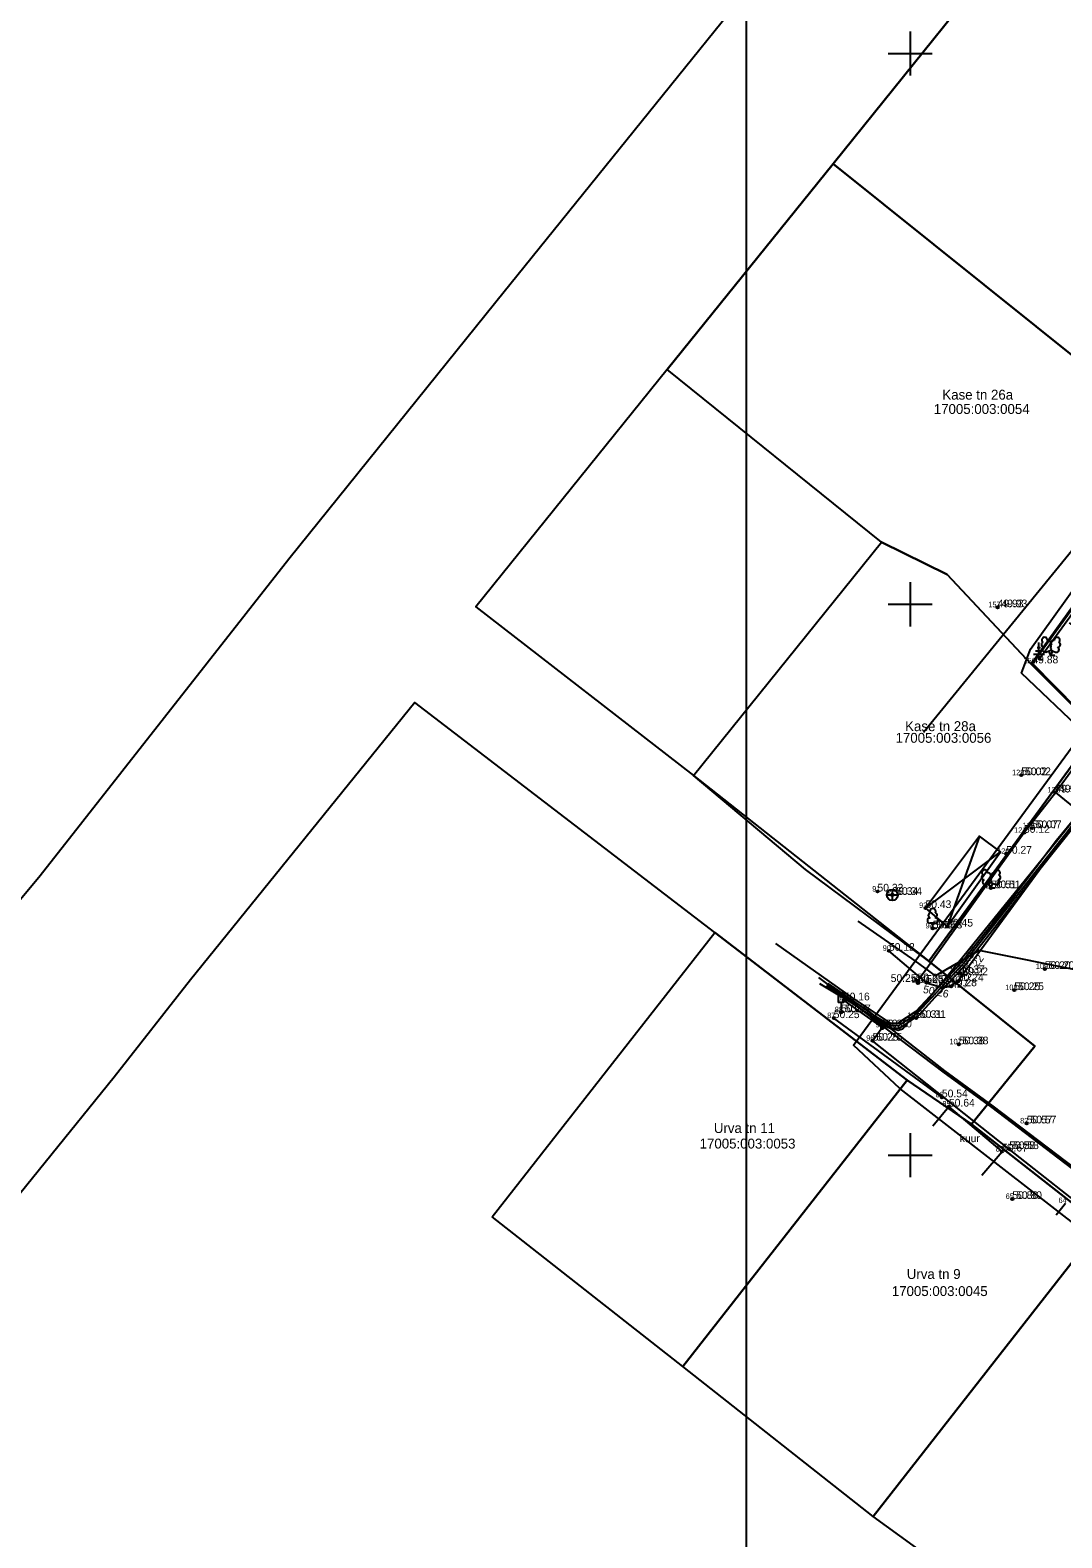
# Model space of a CAD drawing. Extents: x 640876 to 641418, y 6455595 to 6456085.
# Drawn here: x 640970.1 to 641063.8, y 6455815.3 to 6455952.1 of the extents above; entities that cross this region are included whole.
import ezdxf

# ---------------------------------------------------------------- set-up
doc = ezdxf.new("R2010")
doc.units = 0
for name, color, linetype in [('AED', 7, 'Continuous'), ('HALJASTUS', 7, 'Continuous'), ('HOONE', 7, 'Continuous'), ('KKAEV', 7, 'Continuous'), ('KORGUS', 7, 'Continuous'), ('KPKAABEL', 7, 'Continuous'), ('KTRASS', 7, 'Continuous'), ('LIIKLUS', 7, 'Continuous'), ('MOOTKORG', 7, 'Continuous'), ('MOOTMPUNKT', 7, 'Continuous'), ('MOOTNR', 7, 'Continuous'), ('MOOTPIIR', 7, 'Continuous'), ('MPKAABEL', 7, 'Continuous'), ('PIIR', 7, 'Continuous'), ('PUU', 7, 'Continuous'), ('RAJATIS', 7, 'Continuous'), ('SITRASS', 7, 'Continuous'), ('TEE', 7, 'Continuous'), ('VORK', 7, 'Continuous'), ('VORMISTUS', 7, 'Continuous')]:
    doc.layers.add(name, color=color, linetype=linetype)

msp = doc.modelspace()

# ---------------------------------------------------------------- linework, layer by layer
at = {"layer": 'AED'}
for p, q in [((641050.54, 6455865.9), (641050.54, 6455865.65)), ((641050.54, 6455865.9), (641050.79, 6455865.9)), ((641050.54, 6455865.65), (641050.79, 6455865.65)), ((641050.79, 6455865.9), (641050.79, 6455865.65)), ((641047.33, 6455861.72), (641047.33, 6455861.47)), ((641047.33, 6455861.72), (641047.58, 6455861.72)), ((641047.33, 6455861.47), (641047.58, 6455861.47)), ((641047.58, 6455861.72), (641047.58, 6455861.47))]:
    msp.add_line(p, q, dxfattribs=at)
for points in [[(641063.18, 6455882.92), (641067.22, 6455888.43), (641061.1, 6455894.64), (641102.57, 6455951.87), (641103.76, 6455952.95), (641094.12, 6455962.86), (641083.8, 6455973.39)], [(641050.66, 6455865.78), (641060.33, 6455879.26), (641063.18, 6455882.92), (641066.94, 6455879.86)], [(641058.99, 6455850.55), (641046.59, 6455860.39), (641047.46, 6455861.6)], [(641098.57, 6455819.56), (641094.24, 6455822.82), (641082.1, 6455832.09), (641075.84, 6455837.02), (641067.38, 6455843.96), (641058.99, 6455850.55)]]:
    msp.add_lwpolyline(points, dxfattribs=at)
at = {"layer": 'HALJASTUS'}
msp.add_lwpolyline([(641052.88, 6455855.25), (641043.06, 6455862.44)], dxfattribs=at)
at = {"layer": 'HOONE'}
for points in [[(641053.36, 6455870.75), (641058.2, 6455877.53), (641056.28, 6455878.95), (641051.39, 6455872.43), (641058.2, 6455877.53)], [(641056.28, 6455878.95), (641053.36, 6455870.75)], [(641051.39, 6455872.43), (641053.36, 6455870.75)]]:
    msp.add_lwpolyline(points, dxfattribs=at)
at = {"layer": 'KKAEV'}
for p, q in [((641048.38, 6455873.12), (641048.38, 6455874.12)), ((641047.88, 6455873.62), (641048.88, 6455873.62))]:
    msp.add_line(p, q, dxfattribs=at)
msp.add_circle((641048.38, 6455873.62), 0.5, dxfattribs=at)
at = {"layer": 'KORGUS'}
for centre in [(641057.94, 6455899.73), (641060.08, 6455884.49), (641063.18, 6455882.92), (641061.06, 6455879.68), (641048.38, 6455873.62), (641057.32, 6455874.23), (641052.04, 6455870.58), (641062.22, 6455866.9), (641050.66, 6455865.78), (641051.48, 6455865.64), (641054.42, 6455866.52), (641054.72, 6455866.33), (641059.45, 6455864.98), (641043.72, 6455862.97), (641047.46, 6455861.6), (641050.54, 6455862.45), (641046.59, 6455860.39), (641054.41, 6455860.06), (641060.58, 6455852.88), (641058.99, 6455850.55), (641059.27, 6455846.02)]:
    msp.add_circle(centre, 0.1, dxfattribs=at)
at = {"layer": 'KPKAABEL'}
msp.add_lwpolyline([(641067.36, 6455890.93), (641068.5, 6455889.92), (641069.73, 6455887.97), (641069.93, 6455887.18), (641069.78, 6455886.51), (641069.78, 6455886.51), (641066.43, 6455882.38), (641063.29, 6455878.55), (641061.39, 6455876.05), (641058.5, 6455872.31), (641054.68, 6455867.52), (641050.5, 6455863.04), (641048.84, 6455861.94), (641048.28, 6455861.96), (641044.86, 6455864.23), (641037.79, 6455869.22)], dxfattribs=at)
at = {"layer": 'KTRASS'}
msp.add_lwpolyline([(641090.81, 6455936.84), (641051.22, 6455888.36)], dxfattribs=at)
at = {"layer": 'LIIKLUS'}
for p, q in [((641043.47, 6455864.72), (641043.47, 6455863.87)), ((641043.97, 6455864.72), (641043.47, 6455864.72)), ((641043.97, 6455864.72), (641043.97, 6455863.87)), ((641043.97, 6455863.87), (641043.47, 6455863.87)), ((641043.72, 6455863.87), (641043.72, 6455862.97)), ((641043.97, 6455862.97), (641043.72, 6455862.97))]:
    msp.add_line(p, q, dxfattribs=at)
at = {"layer": 'MOOTMPUNKT'}
for centre in [(641057.94, 6455899.73), (641061.1, 6455894.64), (641060.08, 6455884.49), (641063.18, 6455882.92), (641060.33, 6455879.26), (641061.06, 6455879.68), (641058.71, 6455877.36), (641047.03, 6455873.93), (641048.38, 6455873.62), (641057.32, 6455874.23), (641051.39, 6455872.43), (641052.04, 6455870.58), (641053.36, 6455870.75), (641048.07, 6455868.55), (641062.22, 6455866.9), (641050.66, 6455865.78), (641050.7, 6455865.63), (641051.48, 6455865.64), (641054.33, 6455865.78), (641054.42, 6455866.52), (641054.72, 6455866.33), (641043.98, 6455864.05), (641052.94, 6455865.21), (641053.71, 6455865.33), (641059.45, 6455864.98), (641043.72, 6455862.97), (641043.06, 6455862.44), (641047.46, 6455861.6), (641050.54, 6455862.45), (641046.59, 6455860.39), (641054.41, 6455860.06), (641052.88, 6455855.25), (641053.52, 6455854.41), (641060.58, 6455852.88), (641058.99, 6455850.55), (641058.34, 6455850.33), (641059.27, 6455846.02)]:
    msp.add_circle(centre, 0.1, dxfattribs=at)
at = {"layer": 'MOOTPIIR'}
msp.add_lwpolyline([(641136.35, 6455788.31), (641049.07, 6455856.04), (641044.86, 6455859.98), (641065.69, 6455888.44), (641060.1, 6455893.75), (641060.92, 6455895.94), (641100.06, 6455950.48)], dxfattribs=at)
at = {"layer": 'MPKAABEL'}
for points in [[(641067.96, 6455891.74), (641070.7, 6455889.61), (641070.81, 6455888.61), (641070.19, 6455887.41), (641069.57, 6455886.21), (641066.43, 6455882.38), (641061.37, 6455876.11), (641052.96, 6455865.72), (641049.31, 6455861.43), (641048.91, 6455861.3), (641048, 6455861.6), (641046.5, 6455862.62), (641045, 6455863.65), (641041.69, 6455866.14)], [(641068.21, 6455892.08), (641071.09, 6455889.83), (641071.22, 6455888.51), (641069.95, 6455886.1), (641066.87, 6455882.33), (641061.65, 6455875.78), (641057.25, 6455870.13), (641054.99, 6455867.25), (641052.24, 6455864.31), (641050.77, 6455862.72), (641048.96, 6455861.51), (641048.15, 6455861.54), (641047.48, 6455861.95), (641046.81, 6455862.35), (641044.62, 6455863.88), (641042.42, 6455865.4)], [(641068.08, 6455891.91), (641070.89, 6455889.71), (641071.02, 6455888.57), (641069.74, 6455886.1), (641066.6, 6455882.27), (641061.55, 6455875.93), (641057.24, 6455870.41), (641054.83, 6455867.39), (641050.62, 6455862.89), (641048.9, 6455861.73), (641048.21, 6455861.76), (641046.94, 6455862.54), (641044.75, 6455864.06), (641042.56, 6455865.59)], [(641086.41, 6455829.53), (641086.97, 6455831.37), (641086.62, 6455832.08), (641057.43, 6455854.32), (641053.1, 6455857.47), (641049.11, 6455860.51), (641045.12, 6455863.55), (641041.8, 6455865.56)], [(641086.41, 6455829.53), (641087.32, 6455831.35), (641087.2, 6455831.92), (641057.52, 6455854.46), (641053.15, 6455857.64), (641049.7, 6455860.36), (641046.25, 6455863.08), (641042.44, 6455865.41)]]:
    msp.add_lwpolyline(points, dxfattribs=at)
at = {"layer": 'PIIR'}
for points in [[(640876.41, 6455757.97), (640962.33, 6455865.02), (640971.01, 6455875.38), (640993.57, 6455904.12), (641012.36, 6455927.46), (641024.93, 6455943.02), (641037.5, 6455958.58), (641063.25, 6455990.48), (641061.51, 6455993.34), (641084.84, 6455991.92)], [(641074.95, 6455979.64), (641043, 6455940), (641027.94, 6455921.32), (641010.57, 6455899.76), (641030.33, 6455884.46), (641051.68, 6455867.61), (641061.31, 6455859.9), (641055.55, 6455852.8), (641049.71, 6455856.81), (641032.25, 6455870.2), (641005.01, 6455891.09), (640984.64, 6455865.92), (640977.72, 6455857.07), (640952.64, 6455826.1), (640933.13, 6455802.02)]]:
    msp.add_lwpolyline(points, dxfattribs=at)
for points in [[(641074.95, 6455979.64), (641102.26, 6455951.82), (641075.14, 6455914.24), (641043, 6455940)], [(641098.62, 6455818.85), (641093.41, 6455823.22), (641084.65, 6455830.08), (641067.32, 6455843.61), (641055.55, 6455852.8), (641061.31, 6455859.9), (641051.68, 6455867.61), (641067, 6455888.54), (641060.97, 6455894.57), (641075.14, 6455914.24), (641087.11, 6455930.82), (641102.26, 6455951.82), (641160.91, 6455891.99), (641157.02, 6455885.66), (641139.49, 6455869), (641124.05, 6455849.81)], [(641043, 6455940), (641075.14, 6455914.24), (641060.97, 6455894.57), (641053.35, 6455902.7), (641047.4, 6455905.63), (641027.94, 6455921.32)], [(641040.49, 6455875.93), (641030.33, 6455884.46), (641047.4, 6455905.63), (641053.35, 6455902.7), (641060.97, 6455894.57), (641067, 6455888.54), (641051.68, 6455867.61)], [(641012.04, 6455844.39), (641032.25, 6455870.2), (641049.71, 6455856.81), (641029.34, 6455830.8)], [(641029.34, 6455830.8), (641049.71, 6455856.81), (641055.55, 6455852.8), (641067.32, 6455843.61), (641046.64, 6455817.21)], [(641067.32, 6455843.61), (641084.65, 6455830.08), (641064.46, 6455804.29), (641046.64, 6455817.21)]]:
    msp.add_lwpolyline(points, close=True, dxfattribs=at)
at = {"layer": 'PUU'}
for p, q in [((641061.99, 6455895.75), (641061.39, 6455895.75)), ((641061.84, 6455896.05), (641061.54, 6455896.05)), ((641061.69, 6455894.95), (641061.69, 6455896.53)), ((641062.32, 6455895.67), (641062.77, 6455895.85)), ((641062.76, 6455895.34), (641062.58, 6455895.78)), ((641062.76, 6455895.34), (641062.94, 6455895.78)), ((641062.77, 6455895.85), (641063.2, 6455895.67)), ((641062.19, 6455895.45), (641061.19, 6455895.45)), ((641062.05, 6455894.95), (641061.69, 6455894.95)), ((641063.14, 6455895.34), (641062.76, 6455895.34)), ((641056.88, 6455874.56), (641057.33, 6455874.74)), ((641057.32, 6455874.23), (641057.15, 6455874.67)), ((641057.32, 6455874.23), (641057.5, 6455874.67)), ((641057.7, 6455874.23), (641057.32, 6455874.23)), ((641057.33, 6455874.74), (641057.77, 6455874.56)), ((641052.28, 6455871.06), (641051.8, 6455871.06)), ((641052.04, 6455870.58), (641052.04, 6455871.06)), ((641052.42, 6455870.58), (641052.04, 6455870.58))]:
    msp.add_line(p, q, dxfattribs=at)
for points in [[(641102.79, 6455951.54), (641061.69, 6455894.95)], [(641062.77, 6455896.34), (641062.74, 6455896.27), (641062.74, 6455896.25), (641062.76, 6455896.22), (641062.78, 6455896.19), (641062.78, 6455896.17), (641062.77, 6455896.13), (641062.74, 6455896.08), (641062.73, 6455896.05), (641062.74, 6455896.04), (641062.75, 6455896.01), (641062.79, 6455895.95), (641062.79, 6455895.93), (641062.79, 6455895.91), (641062.77, 6455895.88), (641062.77, 6455895.85)], [(641057.33, 6455875.23), (641057.31, 6455875.16), (641057.31, 6455875.14), (641057.32, 6455875.11), (641057.34, 6455875.07), (641057.34, 6455875.05), (641057.33, 6455875.02), (641057.3, 6455874.97), (641057.3, 6455874.94), (641057.3, 6455874.93), (641057.31, 6455874.9), (641057.35, 6455874.84), (641057.35, 6455874.82), (641057.35, 6455874.8), (641057.33, 6455874.76), (641057.33, 6455874.74)]]:
    msp.add_lwpolyline(points, dxfattribs=at)
for centre, radius, start, end in [((641062.2, 6455896.75), 0.256, 111.5027, 232.5173), ((641062.2, 6455896.75), 0.256, 350.4856, 111.5002), ((641063.34, 6455896.75), 0.256, 67.6168, 188.6314), ((641063.34, 6455896.75), 0.256, 306.5997, 67.6143), ((641062.13, 6455896.34), 0.224, 111.4304, 274.4987), ((641062.23, 6455895.9), 0.237, 111.5014, 291.5004), ((641062.54, 6455896.5), 0.224, 308.5041, 111.5725), ((641062.76, 6455896.11), 0.237, 66.7655, 111.5015), ((641063, 6455896.5), 0.225, 67.7016, 230.5126), ((641063.29, 6455895.89), 0.237, 247.6166, 67.6155), ((641063.41, 6455896.33), 0.224, 264.6183, 67.6866), ((641056.69, 6455875.23), 0.224, 111.4304, 274.4987), ((641056.77, 6455875.64), 0.256, 111.5027, 232.5173), ((641056.77, 6455875.64), 0.256, 350.4856, 111.5002), ((641057.1, 6455875.39), 0.224, 308.5041, 111.5725), ((641057.33, 6455874.99), 0.237, 66.7655, 111.5015), ((641057.57, 6455875.39), 0.225, 67.7016, 230.5126), ((641057.9, 6455875.63), 0.256, 67.6168, 188.6314), ((641057.97, 6455875.22), 0.224, 264.6183, 67.6866), ((641057.9, 6455875.63), 0.256, 306.5997, 67.6143), ((641056.8, 6455874.79), 0.237, 111.5014, 291.5004), ((641057.86, 6455874.78), 0.237, 247.6166, 67.6155), ((641052.04, 6455872.1), 0.277, 332.5799, 207.4201), ((641051.8, 6455871.3), 0.238, 90.0016, 269.3953), ((641051.87, 6455871.76), 0.233, 109.0217, 253.1415), ((641052.21, 6455871.76), 0.233, 286.8508, 70.9859), ((641052.28, 6455871.3), 0.238, 270.6047, 89.9984)]:
    msp.add_arc(centre, radius, start, end, dxfattribs=at)
at = {"layer": 'RAJATIS'}
for p, q in [((641052.04, 6455852.67), (641053.52, 6455854.41)), ((641056.5, 6455848.17), (641058.34, 6455850.33)), ((641063.26, 6455844.59), (641064.11, 6455845.65))]:
    msp.add_line(p, q, dxfattribs=at)
msp.add_lwpolyline([(641058.34, 6455850.33), (641053.52, 6455854.41)], dxfattribs=at)
at = {"layer": 'SITRASS'}
msp.add_lwpolyline([(641091.89, 6455854.17), (641091.53, 6455853.73), (641075.03, 6455862.07), (641065.77, 6455866.68), (641056.25, 6455868.57), (641052.29, 6455866.29), (641051.81, 6455866.65), (641050.46, 6455867.64), (641045.27, 6455871.25)], dxfattribs=at)
at = {"layer": 'TEE'}
for points in [[(641051.48, 6455865.64), (641052.94, 6455865.21), (641053.71, 6455865.33), (641054.33, 6455865.78), (641054.72, 6455866.33), (641065.03, 6455880.41), (641066.97, 6455883.06), (641072.38, 6455890.62), (641072.69, 6455891.33), (641072.58, 6455892.09), (641072.19, 6455892.64), (641070.15, 6455894.13), (641064.46, 6455898.31)], [(641051.48, 6455865.64), (641048.07, 6455868.55)], [(641043.98, 6455864.05), (641047.46, 6455861.6)]]:
    msp.add_lwpolyline(points, dxfattribs=at)
at = {"layer": 'VORK'}
for p, q in [((641050, 6455952), (641050, 6455948)), ((641048, 6455950), (641052, 6455950)), ((641050, 6455902), (641050, 6455898)), ((641048, 6455900), (641052, 6455900)), ((641050, 6455852), (641050, 6455848)), ((641048, 6455850), (641052, 6455850))]:
    msp.add_line(p, q, dxfattribs=at)
at = {"layer": 'VORMISTUS'}
msp.add_line((641035.12, 6455709.6), (641035.12, 6456020.09), dxfattribs=at)

# ---------------------------------------------------------------- texts
at = {"layer": 'KORGUS'}
for s, p in [('49.93', (641058.29, 6455899.73)), ('50.02', (641060.43, 6455884.49)), ('49.96', (641063.53, 6455882.92)), ('50.07', (641061.41, 6455879.68)), ('50.34', (641048.73, 6455873.62)), ('50.51', (641057.67, 6455874.23)), ('50.53', (641052.39, 6455870.58)), ('50.20', (641062.57, 6455866.9)), ('50.25', (641048.23, 6455865.72)), ('50.25', (641059.8, 6455864.98)), ('50.27', (641044.07, 6455862.97)), ('50.31', (641050.89, 6455862.45)), ('50.30', (641047.81, 6455861.6)), ('50.25', (641046.94, 6455860.39)), ('50.38', (641054.76, 6455860.06)), ('50.57', (641060.93, 6455852.88)), ('50.58', (641059.34, 6455850.55)), ('50.80', (641059.62, 6455846.02))]:
    msp.add_text(s, height=0.7, dxfattribs=at).set_placement(p)
for s, rotation, p in [('50.37', 52.243, (641054.75, 6455866.72)), ('50.22', 53.5049, (641055.33, 6455865.98)), ('50.26', 348.449, (641051.12, 6455864.74))]:
    msp.add_text(s, height=0.7, rotation=rotation, dxfattribs=at).set_placement(p)
at = {"layer": 'MOOTKORG'}
for s, p in [('49.93', (641057.94, 6455899.73)), ('49.88', (641061.1, 6455894.64)), ('50.02', (641060.08, 6455884.49)), ('49.96', (641063.18, 6455882.92)), ('50.12', (641060.33, 6455879.26)), ('50.07', (641061.06, 6455879.68)), ('50.27', (641058.71, 6455877.36)), ('50.32', (641047.03, 6455873.93)), ('50.34', (641048.38, 6455873.62)), ('50.51', (641057.32, 6455874.23)), ('50.43', (641051.39, 6455872.43)), ('50.53', (641052.04, 6455870.58)), ('50.45', (641053.36, 6455870.75)), ('50.12', (641048.07, 6455868.55)), ('50.37', (641054.42, 6455866.52)), ('50.22', (641054.72, 6455866.33)), ('50.20', (641062.22, 6455866.9)), ('50.25', (641050.66, 6455865.78)), ('50.25', (641050.7, 6455865.63)), ('50.26', (641051.48, 6455865.64)), ('50.27', (641052.94, 6455865.21)), ('50.28', (641053.71, 6455865.33)), ('50.24', (641054.33, 6455865.78)), ('50.25', (641059.45, 6455864.98)), ('50.16', (641043.98, 6455864.05)), ('50.25', (641043.06, 6455862.44)), ('50.27', (641043.72, 6455862.97)), ('50.31', (641050.54, 6455862.45)), ('50.30', (641047.46, 6455861.6)), ('50.25', (641046.59, 6455860.39)), ('50.38', (641054.41, 6455860.06)), ('50.54', (641052.88, 6455855.25)), ('50.64', (641053.52, 6455854.41)), ('50.57', (641060.58, 6455852.88)), ('50.67', (641058.34, 6455850.33)), ('50.58', (641058.99, 6455850.55)), ('50.80', (641059.27, 6455846.02))]:
    msp.add_text(s, height=0.7, dxfattribs=at).set_placement(p)
at = {"layer": 'MOOTNR'}
for s, p in [('157', (641057.09, 6455899.73)), ('156', (641060.28, 6455894.64)), ('128', (641059.25, 6455884.49)), ('121', (641062.46, 6455882.92)), ('124', (641059.43, 6455879.26)), ('125', (641060.21, 6455879.68)), ('126', (641057.89, 6455877.36)), ('91', (641046.55, 6455873.93)), ('92', (641047.78, 6455873.62)), ('127', (641056.47, 6455874.23)), ('93', (641050.81, 6455872.43)), ('94', (641051.39, 6455870.58)), ('95', (641052.76, 6455870.75)), ('90', (641047.5, 6455868.55)), ('105', (641053.57, 6455866.52)), ('109', (641061.4, 6455866.9)), ('99', (641050.09, 6455865.78)), ('98', (641050.13, 6455865.63)), ('100', (641050.65, 6455865.64)), ('101', (641052.22, 6455865.21)), ('102', (641052.86, 6455865.33)), ('103', (641053.5, 6455865.78)), ('104', (641053.82, 6455866.33)), ('108', (641058.63, 6455864.98)), ('89', (641043.4, 6455864.05)), ('87', (641042.46, 6455862.44)), ('88', (641043.15, 6455862.97)), ('106', (641049.72, 6455862.45)), ('97', (641046.86, 6455861.6)), ('96', (641046.01, 6455860.39)), ('107', (641053.56, 6455860.06)), ('86', (641052.3, 6455855.25)), ('85', (641052.92, 6455854.41)), ('82', (641059.98, 6455852.88)), ('83', (641057.76, 6455850.33)), ('84', (641058.34, 6455850.55)), ('65', (641058.67, 6455846.02)), ('64', (641063.46, 6455845.65))]:
    msp.add_text(s, height=0.5, dxfattribs=at).set_placement(p)
at = {"layer": 'PIIR'}
for s, p in [('Kase tn 26a', (641052.92, 6455918.58)), ('Kase tn 28a', (641049.54, 6455888.49)), ('17005:003:0056', (641048.67, 6455887.43)), ('Urva tn 11', (641032.17, 6455852.01)), ('17005:003:0053', (641030.88, 6455850.6)), ('Urva tn 9', (641049.69, 6455838.76)), ('17005:003:0045', (641048.33, 6455837.21))]:
    msp.add_text(s, height=0.9, dxfattribs=at).set_placement(p)
msp.add_text('17005:003:0054', height=0.9, rotation=360, dxfattribs=at).set_placement((641052.14, 6455917.28))
at = {"layer": 'RAJATIS'}
msp.add_text('kuur', height=0.7, dxfattribs=at).set_placement((641054.5, 6455851.18))

doc.saveas('drawing.dxf')
